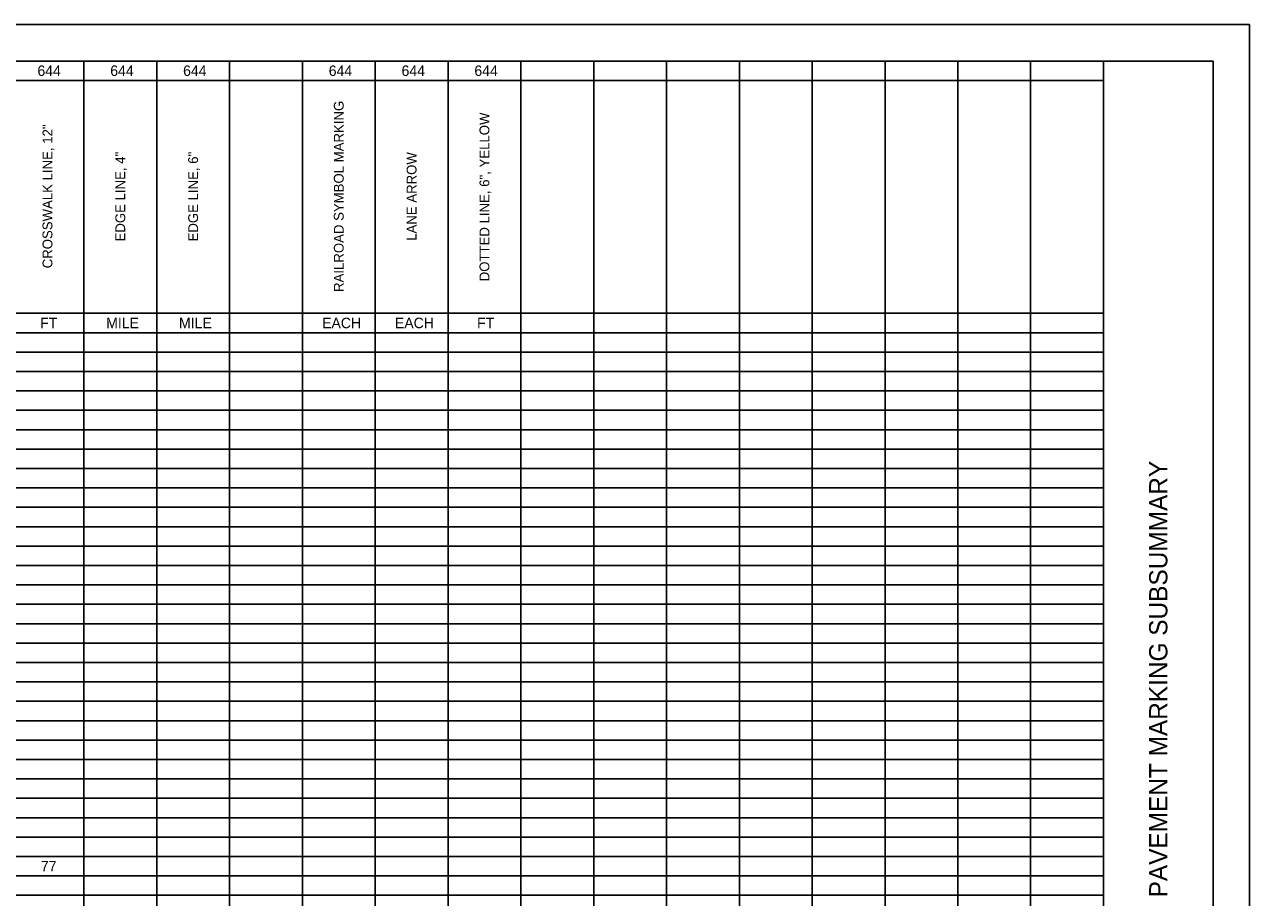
# Model space of a CAD drawing. Extents: x 0 to 34, y 0 to 22.
# Drawn here: x 17.21 to 34, y 10.04 to 22 of the extents above; entities that cross this region are included whole.
import ezdxf

# ---------------------------------------------------------------- set-up
doc = ezdxf.new("R2010")
doc.units = 0
for name, color, linetype in [('SH_Border', 7, 'Continuous'), ('SH_Cut_Line', 7, 'Continuous'), ('SH_Data', 7, 'Continuous'), ('SH_Text', 7, 'Continuous')]:
    doc.layers.add(name, color=color, linetype=linetype)

msp = doc.modelspace()

# ---------------------------------------------------------------- linework, layer by layer
at = {"layer": 'SH_Border'}
msp.add_line((32, 0.5), (32, 21.5), dxfattribs=at)
msp.add_lwpolyline([(1.5, 21.5), (33.5, 21.5), (33.5, 0.5), (1.5, 0.5)], close=True, dxfattribs=at)
at = {"layer": 'SH_Cut_Line'}
msp.add_lwpolyline([(0, 0), (34, 0), (34, 22), (0, 22)], close=True, dxfattribs=at)
at = {"layer": 'SH_Text'}
for p, q in [((1.5, 21.5), (31.999, 21.5)), ((18.027, 21.5), (18.027, 0.5)), ((19.025, 21.5), (19.025, 0.5)), ((20.023, 21.5), (20.023, 0.5)), ((21.021, 21.5), (21.021, 0.5)), ((22.019, 21.5), (22.019, 0.5)), ((23.017, 21.5), (23.017, 0.5)), ((24.015, 21.5), (24.015, 0.5)), ((25.013, 21.5), (25.013, 0.5)), ((26.011, 21.5), (26.011, 0.5)), ((27.009, 21.5), (27.009, 0.5)), ((28.007, 21.5), (28.007, 0.5)), ((29.005, 21.5), (29.005, 0.5)), ((30.003, 21.5), (30.003, 0.5)), ((31.001, 21.5), (31.001, 0.5)), ((31.999, 21.5), (31.999, 0.5)), ((9.044, 21.234), (31.999, 21.234)), ((9.044, 18.044), (31.999, 18.044)), ((1.5, 17.778), (31.999, 17.778)), ((1.5, 17.513), (31.999, 17.513)), ((1.5, 17.247), (31.999, 17.247)), ((1.5, 16.981), (31.999, 16.981)), ((1.5, 16.715), (31.999, 16.715)), ((1.5, 16.449), (31.999, 16.449)), ((1.5, 16.184), (31.999, 16.184)), ((1.5, 15.918), (31.999, 15.918)), ((1.5, 15.652), (31.999, 15.652)), ((1.5, 15.386), (31.999, 15.386)), ((1.5, 15.12), (31.999, 15.12)), ((1.5, 14.854), (31.999, 14.854)), ((1.5, 14.589), (31.999, 14.589)), ((1.5, 14.323), (31.999, 14.323)), ((1.5, 14.057), (31.999, 14.057)), ((1.5, 13.791), (31.999, 13.791)), ((1.5, 13.525), (31.999, 13.525)), ((1.5, 13.259), (31.999, 13.259)), ((1.5, 12.994), (31.999, 12.994)), ((1.5, 12.728), (31.999, 12.728)), ((1.5, 12.462), (31.999, 12.462)), ((1.5, 12.196), (31.999, 12.196)), ((1.5, 11.93), (31.999, 11.93)), ((1.5, 11.665), (31.999, 11.665)), ((1.5, 11.399), (31.999, 11.399)), ((1.5, 11.133), (31.999, 11.133)), ((1.5, 10.867), (31.999, 10.867)), ((1.5, 10.601), (31.999, 10.601)), ((1.5, 10.335), (31.999, 10.335)), ((1.5, 10.07), (31.999, 10.07))]:
    msp.add_line(p, q, dxfattribs=at)

# ---------------------------------------------------------------- texts
at = {"layer": 'SH_Data'}
msp.add_text('PAVEMENT MARKING SUBSUMMARY', height=0.25, rotation=90, dxfattribs=at).set_placement((32.875, 10.041))
at = {"layer": 'SH_Text'}
for s, p in [('644', (17.39, 21.295)), ('644', (18.388, 21.295)), ('644', (19.386, 21.295)), ('644', (21.382, 21.295)), ('644', (22.38, 21.295)), ('644', (23.378, 21.295)), ('FT', (17.426, 17.839)), ('MILE', (18.332, 17.839)), ('MILE', (19.33, 17.839)), ('EACH', (21.291, 17.839)), ('EACH', (22.289, 17.839)), ('FT', (23.414, 17.839)), ('77', (17.437, 10.396))]:
    msp.add_text(s, height=0.1439, dxfattribs=at).set_placement(p)
for s, height, p in [('RAILROAD SYMBOL MARKING', 0.13503, (21.587, 18.336)), ('DOTTED LINE, 6", YELLOW', 0.13503, (23.583, 18.482)), ('CROSSWALK LINE, 12"', 0.13503, (17.595, 18.66)), ('EDGE LINE, 4"', 0.13503, (18.593, 19.028)), ('EDGE LINE, 6"', 0.13503, (19.591, 19.028)), ('LANE ARROW', 0.135, (22.585, 19.037))]:
    msp.add_text(s, height=height, rotation=90, dxfattribs=at).set_placement(p)

doc.saveas('drawing.dxf')
